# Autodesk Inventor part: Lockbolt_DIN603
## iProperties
Author: Borre Hartviksen
Shininess: 25.0
PropertySet Name: _Private Model Information
Created: 2001-04
Part Number: Lockbolt_DIN603
Material: A4
Description: LockBolt M8x30
Vendor: DIN 603
Document SubType Name: Modeling
Designer: Borre Hartviksen
Control State: 0
Master: False
Checked Out: False
PropertySet Name: Design Tracking Control
Density: 7.750000000000001
Volumn: 2.294690184718723
Area: 14.304310721642294
PropertySet Name: Model Information
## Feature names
1. Extrusion2
2. Chamfer1
3. Extrusion4
4. Fillet1
5. Revolution3
